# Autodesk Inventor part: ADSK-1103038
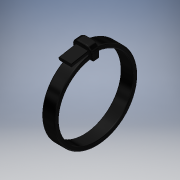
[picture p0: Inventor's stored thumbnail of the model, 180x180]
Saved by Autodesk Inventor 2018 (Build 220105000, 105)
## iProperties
Shininess: 41.0
Length Units: 11272
Angle Units: 11279
Time Units: 11290
Mass Units: 11286
Length Display Precision: 4
Angle Display Precision: 2
Compacted: True
Created: 2000-08
Part Number: ADSK-1103038
Document SubType Name: Modeling
Description: METAL TIE
Mass: 0.127833 g
Surface Area: 3.35412 cm^2
Volume: 0.113127 cm^3
Density: 1.13 g/cm^3
Material: Nylon-6/6
Appearance: Glossy - Black
Density: 0.0
Volumn: 0.0
Area: 0.0
PropertySet Name: Model Information
Control State: 0
Master: False
Checked Out: False
Author: Autodesk, Inc.
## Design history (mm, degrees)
node "Revolution1" dims "d3" = 270 deg
  sketch "Sketch3"
    geometry: L1 (-13.841, 6.211)-(-11.301, 6.211); L2 (-11.301, 6.211)-(-11.301, 5.365); L3 (-11.301, 5.365)-(-13.841, 5.365); L4 (-13.841, 5.365)-(-13.841, 6.211); L5 (-15.021, -1.62)-(-10.408, -1.62)
    constraints: 10 end point, 2 parallel, 2 perpendicular, 1 horizontal
    dimensions: "d0" = 2.54 distance of L1.start L1.end; "d1" = 0.84667 distance between parallel lines of L1 L3 (= 0.333333 x d0); "d2" = 13.97 diameter of L3 L5
workaxis "Work Axis1"
node "Revolution2" dims "d5" = 90 deg
  sketch "Sketch4"
    geometry: L1 (0, 0)-(2.54, 0) reference; L2 (0, -0.847)-(0, 0) reference; L3 (2.54, -0.847)-(0, -0.847) reference; L4 (2.54, 0)-(2.54, -0.847) reference; L5 (-1.305, -8.467)-(3.845, -8.467)
    constraints: 2 end point, 1 perpendicular
    dimensions: "d4" = 7.62 distance between parallel lines of L3 L5
node "Revolution3" dims "d6" = 10 deg
  sketch "Sketch5"
    geometry: L1 (2.54, 0.608)-(0, 0.608) reference; L2 (0, 0)-(0, 0.608) reference; L3 (2.54, 0)-(0, 0) reference; L4 (2.54, 0.608)-(2.54, 0) reference; L5 (-0.661, 0)-(3.094, 0); L6 (3.094, 0)-(3.094, 2.551); L7 (3.094, 2.551)-(-0.661, 2.551); L8 (-0.661, 2.551)-(-0.661, 0); L9 (3.845, -6.985)-(-1.412, -6.985) reference
    constraints: 8 end point, 2 parallel, 1 horizontal, 1 perpendicular
node "Fillet1" dims "d7" = 1.27
node "Extrusion1" dims "d8" = 3.175, "d9" = 0
  sketch "Sketch6"
    geometry: L1 (0, 0.18)-(2.524, 0.18); L2 (2.524, 0.18)-(2.524, 0.866); L3 (2.524, 0.866)-(0, 0.866); L4 (0, 0.866)-(0, 0.18)
    constraints: 8 end point, 2 parallel, 1 horizontal, 1 perpendicular
node "Fillet2" dims "d10" = 0.254
node "Fillet3" dims "d11" = 0.254
node "Fillet4" dims "d12" = 0.254
body "Solid1"
